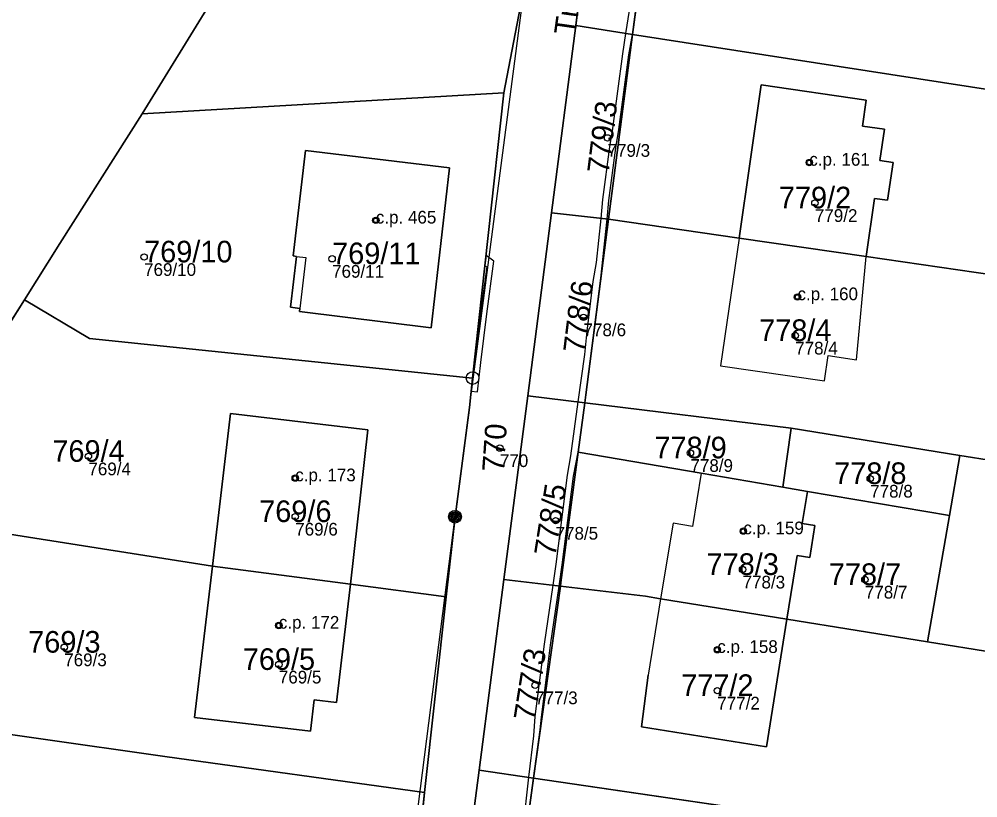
# Model space of a CAD drawing. Extents: x -603967 to -594699, y -1179315 to -1165625.
# Drawn here: x -597987.7 to -597912.3, y -1172213.4 to -1172152.2 of the extents above; entities that cross this region are included whole.
import ezdxf

# ---------------------------------------------------------------- set-up
doc = ezdxf.new("R2010")
doc.units = 0
for name, color, linetype in [('Definiční body', 7, 'Continuous'), ('Hranice parcel', 7, 'Continuous'), ('Parcelní čísla', 7, 'Continuous'), ('Polygon budovy', 7, 'Continuous'), ('Polygon parcely', 7, 'Continuous'), ('Pop  PČ popisy', 7, 'Continuous'), ('Poz předměty', 7, 'Continuous'), ('Vnitřní kresba', 7, 'Continuous'), ('Věcná břemena k části', 7, 'Continuous'), ('Značky bodu BP', 7, 'Continuous'), ('Značky budov', 7, 'Continuous')]:
    doc.layers.add(name, color=color, linetype=linetype)

msp = doc.modelspace()

# ---------------------------------------------------------------- linework, layer by layer
at = {"layer": 'Definiční body'}
for centre in [(-597941.45, -1172161.52994), (-597925.58, -1172163.46994), (-597925.14, -1172166.64994), (-597959.68, -1172168.01994), (-597977.91, -1172170.89994), (-597963.12, -1172171.03994), (-597926.51, -1172174.04994), (-597943.34, -1172175.63994), (-597926.69, -1172177.07994), (-597982.29, -1172186.57994), (-597949.92, -1172185.92994), (-597934.93, -1172186.30994), (-597966.02, -1172188.28994), (-597920.79, -1172188.32994), (-597966.02, -1172191.31994), (-597945.54, -1172191.63994), (-597930.77, -1172192.45994), (-597930.83, -1172195.47994), (-597921.21, -1172196.26994), (-597967.31, -1172199.87994), (-597984.19, -1172201.58994), (-597932.82, -1172201.78994), (-597967.31, -1172202.94994), (-597947.15, -1172204.57994), (-597932.82, -1172204.99994)]:
    msp.add_circle(centre, 0.25, dxfattribs=at)
at = {"layer": 'Hranice parcel'}
for p, q in [((-597978.05, -1172159.64), (-597964.77, -1172138.05)), ((-597943.96, -1172152.7), (-597941.99, -1172137.45)), ((-597937.48, -1172138.07), (-597939.48, -1172153.39)), ((-597949.61, -1172157.98), (-597947.92, -1172149.24)), ((-597945.87, -1172167.43), (-597943.96, -1172152.7)), ((-597939.48, -1172153.39), (-597943.96, -1172152.7)), ((-597941.37, -1172167.93), (-597939.48, -1172153.39)), ((-597939.48, -1172153.39), (-597904.76, -1172158.77)), ((-597978.05, -1172159.64), (-597949.61, -1172157.98)), ((-597949.61, -1172157.98), (-597952.07, -1172180.42)), ((-597947.73, -1172181.82), (-597945.87, -1172167.43)), ((-597941.37, -1172167.93), (-597945.87, -1172167.43)), ((-597998, -1172191.21), (-597987.33, -1172174.26)), ((-597949.6, -1172196.27), (-597947.73, -1172181.82)), ((-597943.24, -1172182.37), (-597947.73, -1172181.82)), ((-597943.76, -1172186.24), (-597943.24, -1172182.37)), ((-597943.24, -1172182.37), (-597927, -1172184.35)), ((-597927, -1172184.35), (-597927.66, -1172189)), ((-597927, -1172184.35), (-597913.74, -1172186.5)), ((-597943.76, -1172186.24), (-597945.12, -1172196.5)), ((-597913.74, -1172186.5), (-597914.56, -1172191.24)), ((-597925.73, -1172189.33), (-597927.66, -1172189)), ((-597914.56, -1172191.24), (-597925.73, -1172189.33)), ((-597914.56, -1172191.24), (-597916.27, -1172201.17)), ((-597972.54, -1172195.22), (-597993.35, -1172191.94)), ((-597961.68, -1172196.64), (-597972.54, -1172195.22)), ((-597954.14, -1172197.63), (-597961.68, -1172196.64)), ((-597951.54, -1172211.26), (-597949.6, -1172196.27)), ((-597945.16, -1172196.79), (-597949.6, -1172196.27)), ((-597945.16, -1172196.79), (-597947.27, -1172211.88)), ((-597945.12, -1172196.5), (-597945.16, -1172196.79)), ((-597955.84, -1172213.01), (-597954.14, -1172197.63)), ((-597927.34, -1172199.38), (-597937.28, -1172197.77)), ((-597916.27, -1172201.17), (-597927.34, -1172199.38)), ((-597947.27, -1172211.88), (-597951.54, -1172211.26)), ((-597949.23, -1172226.15), (-597947.27, -1172211.88)), ((-597947.27, -1172211.88), (-597911.97, -1172217.04)), ((-597955.84, -1172213.01), (-597957.24, -1172226))]:
    msp.add_line(p, q, dxfattribs=at)
for points in [[(-597987.33, -1172174.26), (-597984.55, -1172169.83), (-597978.05, -1172159.64)], [(-597965.65, -1172174.94), (-597966.39, -1172174.85), (-597965.93, -1172170.85), (-597966.18, -1172170.82), (-597965.22, -1172162.52), (-597953.89, -1172163.89), (-597955.34, -1172176.47), (-597965.68, -1172175.19), (-597965.65, -1172174.94)], [(-597941.37, -1172167.93), (-597943.16, -1172181.73), (-597943.24, -1172182.37)], [(-597903.91, -1172173.35), (-597909.56, -1172172.53), (-597921.11, -1172170.86), (-597931.11, -1172169.41), (-597941.37, -1172167.93)], [(-597952.07, -1172180.42), (-597982.2, -1172177.32), (-597987.33, -1172174.26)], [(-597954.14, -1172197.63), (-597953.45, -1172191.33), (-597952.32, -1172182.74), (-597952.07, -1172180.42)], [(-597972.54, -1172195.22), (-597971.12, -1172183.2), (-597960.3, -1172184.48), (-597961.68, -1172196.64)], [(-597927.66, -1172189), (-597934.1, -1172187.9), (-597943.76, -1172186.24)], [(-597905.59, -1172187.82), (-597908.43, -1172187.36), (-597913.74, -1172186.5)], [(-597927.34, -1172199.38), (-597926.54, -1172194.37), (-597925.55, -1172194.53), (-597925.14, -1172192.01), (-597926.13, -1172191.85), (-597925.73, -1172189.33)], [(-597961.68, -1172196.64), (-597962.78, -1172205.93), (-597964.52, -1172205.72), (-597964.82, -1172208.2), (-597973.95, -1172207.12), (-597972.54, -1172195.22)], [(-597937.28, -1172197.77), (-597938.47, -1172197.57), (-597945.16, -1172196.79)], [(-597910.16, -1172202.16), (-597911.07, -1172202.01), (-597916.27, -1172201.17)], [(-597996.18, -1172207.34), (-597976.28, -1172210.18), (-597955.84, -1172213.01)], [(-597953.39, -1172225.43), (-597952.04, -1172215.07), (-597951.54, -1172211.26)]]:
    msp.add_lwpolyline(points, dxfattribs=at)
at = {"layer": 'Polygon budovy'}
for points in [[(-597931.11, -1172169.41), (-597921.11, -1172170.86), (-597920.46, -1172166.29), (-597919.42, -1172166.44), (-597918.99, -1172163.47), (-597920.03, -1172163.32), (-597919.67, -1172160.85), (-597921.4, -1172160.6), (-597921.11, -1172158.57), (-597929.37, -1172157.37)], [(-597966.18, -1172170.82), (-597965.93, -1172170.85), (-597965.19, -1172170.93), (-597965.65, -1172174.94), (-597965.68, -1172175.19), (-597955.34, -1172176.47), (-597953.89, -1172163.89), (-597965.22, -1172162.52)], [(-597931.11, -1172169.41), (-597932.56, -1172179.46), (-597924.39, -1172180.63), (-597924.11, -1172178.65), (-597921.88, -1172178.98), (-597921.11, -1172170.86)], [(-597972.54, -1172195.22), (-597961.68, -1172196.64), (-597960.3, -1172184.48), (-597971.12, -1172183.2)], [(-597927.34, -1172199.38), (-597926.54, -1172194.37), (-597925.55, -1172194.53), (-597925.14, -1172192.01), (-597926.13, -1172191.85), (-597925.73, -1172189.33), (-597927.66, -1172189), (-597934.1, -1172187.9), (-597934.78, -1172192.09), (-597936.3, -1172191.84), (-597937.28, -1172197.77)], [(-597973.95, -1172207.12), (-597964.82, -1172208.2), (-597964.52, -1172205.72), (-597962.78, -1172205.93), (-597961.68, -1172196.64), (-597972.54, -1172195.22)], [(-597938.78, -1172207.86), (-597928.94, -1172209.43), (-597927.34, -1172199.38), (-597937.28, -1172197.77), (-597938.25, -1172203.79)]]:
    msp.add_lwpolyline(points, close=True, dxfattribs=at)
at = {"layer": 'Polygon parcely'}
for points in [[(-597964.77, -1172138.05), (-597950.03, -1172113.6), (-597977.95, -1172106.04), (-598024.89, -1172188.58), (-597998, -1172191.21), (-597987.33, -1172174.26), (-597984.55, -1172169.83), (-597978.05, -1172159.64)], [(-597943.37, -1172116.01), (-597944.91, -1172113.97), (-597946.07, -1172113.66), (-597949.44, -1172112.75), (-597950.03, -1172113.6), (-597964.77, -1172138.05), (-597978.05, -1172159.64), (-597949.61, -1172157.98), (-597947.92, -1172149.24)], [(-597941.99, -1172137.45), (-597943.96, -1172152.7), (-597939.48, -1172153.39), (-597937.48, -1172138.07)], [(-597937.48, -1172138.07), (-597939.48, -1172153.39), (-597904.76, -1172158.77), (-597904.04, -1172153.64), (-597902.59, -1172143.24), (-597906.05, -1172142.72), (-597916.63, -1172141.16), (-597926.68, -1172139.67)], [(-597939.48, -1172153.39), (-597943.96, -1172152.7), (-597945.87, -1172167.43), (-597941.37, -1172167.93)], [(-597941.37, -1172167.93), (-597931.11, -1172169.41), (-597921.11, -1172170.86), (-597909.56, -1172172.53), (-597903.91, -1172173.35), (-597902.56, -1172161.8), (-597902.22, -1172159.16), (-597904.76, -1172158.77), (-597939.48, -1172153.39)], [(-597978.05, -1172159.64), (-597984.55, -1172169.83), (-597987.33, -1172174.26), (-597982.2, -1172177.32), (-597952.07, -1172180.42), (-597949.61, -1172157.98)], [(-597965.65, -1172174.94), (-597965.68, -1172175.19), (-597955.34, -1172176.47), (-597953.89, -1172163.89), (-597965.22, -1172162.52), (-597966.18, -1172170.82), (-597965.93, -1172170.85), (-597966.39, -1172174.85)], [(-597965.65, -1172174.94), (-597966.39, -1172174.85), (-597965.93, -1172170.85), (-597966.18, -1172170.82), (-597965.22, -1172162.52), (-597953.89, -1172163.89), (-597955.34, -1172176.47), (-597965.68, -1172175.19)], [(-597945.87, -1172167.43), (-597947.73, -1172181.82), (-597943.24, -1172182.37), (-597943.16, -1172181.73), (-597941.37, -1172167.93)], [(-597927, -1172184.35), (-597913.74, -1172186.5), (-597908.43, -1172187.36), (-597905.59, -1172187.82), (-597905.04, -1172183.09), (-597903.91, -1172173.35), (-597909.56, -1172172.53), (-597921.11, -1172170.86), (-597931.11, -1172169.41), (-597941.37, -1172167.93), (-597943.16, -1172181.73), (-597943.24, -1172182.37)], [(-597953.45, -1172191.33), (-597952.32, -1172182.74), (-597952.07, -1172180.42), (-597982.2, -1172177.32), (-597987.33, -1172174.26), (-597998, -1172191.21), (-597993.35, -1172191.94), (-597972.54, -1172195.22), (-597971.12, -1172183.2), (-597960.3, -1172184.48), (-597961.68, -1172196.64), (-597954.14, -1172197.63)], [(-597943.24, -1172182.37), (-597947.73, -1172181.82), (-597949.6, -1172196.27), (-597945.16, -1172196.79), (-597945.12, -1172196.5), (-597943.76, -1172186.24)], [(-597943.24, -1172182.37), (-597943.76, -1172186.24), (-597934.1, -1172187.9), (-597927.66, -1172189), (-597927, -1172184.35)], [(-597961.68, -1172196.64), (-597960.3, -1172184.48), (-597971.12, -1172183.2), (-597972.54, -1172195.22)], [(-597927.66, -1172189), (-597925.73, -1172189.33), (-597914.56, -1172191.24), (-597913.74, -1172186.5), (-597927, -1172184.35)], [(-597943.76, -1172186.24), (-597945.12, -1172196.5), (-597945.16, -1172196.79), (-597938.47, -1172197.57), (-597937.28, -1172197.77), (-597927.34, -1172199.38), (-597926.54, -1172194.37), (-597925.55, -1172194.53), (-597925.14, -1172192.01), (-597926.13, -1172191.85), (-597925.73, -1172189.33), (-597927.66, -1172189), (-597934.1, -1172187.9)], [(-597916.27, -1172201.17), (-597911.07, -1172202.01), (-597910.16, -1172202.16), (-597871.52, -1172208.41), (-597869.04, -1172193.74), (-597905.59, -1172187.82), (-597908.43, -1172187.36), (-597913.74, -1172186.5), (-597914.56, -1172191.24)], [(-597925.73, -1172189.33), (-597926.13, -1172191.85), (-597925.14, -1172192.01), (-597925.55, -1172194.53), (-597926.54, -1172194.37), (-597927.34, -1172199.38), (-597916.27, -1172201.17), (-597914.56, -1172191.24)], [(-597964.82, -1172208.2), (-597973.95, -1172207.12), (-597972.54, -1172195.22), (-597993.35, -1172191.94), (-598002.14, -1172206.39), (-597996.18, -1172207.34), (-597976.28, -1172210.18), (-597955.84, -1172213.01), (-597954.14, -1172197.63), (-597961.68, -1172196.64), (-597962.78, -1172205.93), (-597964.52, -1172205.72)], [(-597972.54, -1172195.22), (-597973.95, -1172207.12), (-597964.82, -1172208.2), (-597964.52, -1172205.72), (-597962.78, -1172205.93), (-597961.68, -1172196.64)], [(-597949.6, -1172196.27), (-597951.54, -1172211.26), (-597947.27, -1172211.88), (-597945.16, -1172196.79)], [(-597911.07, -1172202.01), (-597916.27, -1172201.17), (-597927.34, -1172199.38), (-597937.28, -1172197.77), (-597938.47, -1172197.57), (-597945.16, -1172196.79), (-597947.27, -1172211.88), (-597911.97, -1172217.04), (-597910.16, -1172202.16)], [(-597964.63, -1172224.94), (-597957.24, -1172226), (-597955.84, -1172213.01), (-597976.28, -1172210.18), (-597996.18, -1172207.34), (-597997.29, -1172216.06), (-597975.12, -1172223.43), (-597973.83, -1172214.15), (-597963.34, -1172215.61), (-597963.78, -1172218.82), (-597962.6, -1172218.99), (-597962.98, -1172221.7), (-597964.16, -1172221.58)], [(-597949.23, -1172226.15), (-597947.27, -1172211.88), (-597951.54, -1172211.26), (-597952.04, -1172215.07), (-597953.39, -1172225.43)], [(-597929.15, -1172229.61), (-597913.82, -1172232.25), (-597911.97, -1172217.04), (-597947.27, -1172211.88), (-597949.23, -1172226.15), (-597947.84, -1172226.39), (-597940.09, -1172227.73), (-597938.27, -1172217.37), (-597927.36, -1172219.26)]]:
    msp.add_lwpolyline(points, close=True, dxfattribs=at)
for points in [[(-597952.04, -1172215.07), (-597951.54, -1172211.26), (-597949.6, -1172196.27), (-597947.73, -1172181.82), (-597945.87, -1172167.43), (-597943.96, -1172152.7), (-597941.99, -1172137.45)], [(-597947.92, -1172149.24), (-597949.61, -1172157.98), (-597952.07, -1172180.42), (-597952.32, -1172182.74), (-597953.45, -1172191.33), (-597954.14, -1172197.63), (-597955.84, -1172213.01), (-597957.24, -1172226)]]:
    msp.add_lwpolyline(points, dxfattribs=at)
at = {"layer": 'Poz předměty'}
for p, q in [((-597953.45, -1172191.33), (-597947.92, -1172149.24)), ((-597958.82, -1172233.47), (-597953.45, -1172191.33))]:
    msp.add_line(p, q, dxfattribs=at)
for radius in [0.5, 0.4, 0.3, 0.2, 0.1]:
    msp.add_circle((-597953.45343, -1172191.32988), radius, dxfattribs=at)
at = {"layer": 'Vnitřní kresba'}
for p, q in [((-597931.11, -1172169.41), (-597929.37, -1172157.37)), ((-597929.37, -1172157.37), (-597921.11, -1172158.57)), ((-597921.11, -1172158.57), (-597921.4, -1172160.6)), ((-597921.4, -1172160.6), (-597919.67, -1172160.85)), ((-597919.67, -1172160.85), (-597920.03, -1172163.32)), ((-597920.03, -1172163.32), (-597918.99, -1172163.47)), ((-597918.99, -1172163.47), (-597919.42, -1172166.44)), ((-597920.46, -1172166.29), (-597921.11, -1172170.86)), ((-597919.42, -1172166.44), (-597920.46, -1172166.29)), ((-597931.11, -1172169.41), (-597932.56, -1172179.46)), ((-597965.93, -1172170.85), (-597965.19, -1172170.93)), ((-597965.19, -1172170.93), (-597965.65, -1172174.94)), ((-597921.88, -1172178.98), (-597921.11, -1172170.86)), ((-597924.39, -1172180.63), (-597924.11, -1172178.65)), ((-597924.11, -1172178.65), (-597921.88, -1172178.98)), ((-597932.56, -1172179.46), (-597924.39, -1172180.63)), ((-597934.1, -1172187.9), (-597934.78, -1172192.09)), ((-597936.3, -1172191.84), (-597937.28, -1172197.77)), ((-597934.78, -1172192.09), (-597936.3, -1172191.84)), ((-597937.28, -1172197.77), (-597938.25, -1172203.79)), ((-597927.34, -1172199.38), (-597928.94, -1172209.43)), ((-597938.78, -1172207.86), (-597938.25, -1172203.79)), ((-597928.94, -1172209.43), (-597938.78, -1172207.86))]:
    msp.add_line(p, q, dxfattribs=at)
at = {"layer": 'Věcná břemena k části'}
for points in [[(-597948.69, -1172222.24), (-597947.27, -1172211.88), (-597946.74, -1172208.08), (-597946.66, -1172207.09), (-597945.93, -1172201.42), (-597945.26, -1172196.78), (-597945.02, -1172195.12), (-597944.14, -1172188.14), (-597943.76, -1172186.24), (-597943.24, -1172182.37), (-597943.16, -1172181.73), (-597941.97, -1172172.57), (-597941.49, -1172167.92), (-597941.34, -1172166.45), (-597940.79, -1172162.32), (-597940.57, -1172160.87), (-597939.78, -1172155), (-597939.48, -1172153.39), (-597937.48, -1172138.07)], [(-597939.37, -1172149.02), (-597940.03, -1172153.31), (-597940.28, -1172154.92), (-597941.07, -1172160.79), (-597941.29, -1172162.24), (-597941.84, -1172166.39), (-597941.99, -1172167.86), (-597942.35, -1172171.33), (-597942.62, -1172172.83), (-597943.08, -1172176.74), (-597943.27, -1172178.56), (-597943.79, -1172182.3), (-597944.37, -1172186.55), (-597944.64, -1172188.06), (-597945.52, -1172195.06), (-597945.76, -1172196.72), (-597946.43, -1172201.36), (-597947.16, -1172207.03), (-597947.28, -1172208.56), (-597947.66, -1172211.82), (-597948.12, -1172215.85)]]:
    msp.add_lwpolyline(points, dxfattribs=at)
msp.add_lwpolyline([(-597952.18, -1172181.44), (-597951.67, -1172181.5), (-597951.43, -1172179.19), (-597950.95, -1172175.37), (-597950.39, -1172171.23), (-597951.01, -1172170.77), (-597951.1, -1172171.58), (-597950.96, -1172171.67), (-597951.45, -1172175.31), (-597951.93, -1172179.13), (-597952.07, -1172180.42)], close=True, dxfattribs=at)
at = {"layer": 'Značky bodu BP'}
for radius in [0.5, 0.0303]:
    msp.add_circle((-597952.07, -1172180.41988), radius, dxfattribs=at)
at = {"layer": 'Značky budov'}
for centre in [(-597925.5868, -1172163.46916), (-597959.6868, -1172168.01916), (-597926.5168, -1172174.04916), (-597966.0268, -1172188.28916), (-597930.7768, -1172192.45916), (-597967.3168, -1172199.87916), (-597932.8268, -1172201.78916)]:
    msp.add_circle(centre, 0.175, dxfattribs=at)

# ---------------------------------------------------------------- texts
at = {"layer": 'Definiční body'}
for s, p in [('779/3', (-597941.45, -1172163.019)), ('c.p. 161', (-597925.58, -1172163.72)), ('c.p. 465', (-597959.68, -1172168.27)), ('779/2', (-597925.14, -1172168.139)), ('769/10', (-597977.91, -1172172.389)), ('769/11', (-597963.12, -1172172.529)), ('c.p. 160', (-597926.51, -1172174.3)), ('778/6', (-597943.34, -1172177.129)), ('778/4', (-597926.69, -1172178.569)), ('770', (-597949.92, -1172187.419)), ('769/4', (-597982.29, -1172188.069)), ('778/9', (-597934.93, -1172187.799)), ('c.p. 173', (-597966.02, -1172188.54)), ('778/8', (-597920.79, -1172189.819)), ('769/6', (-597966.02, -1172192.809)), ('778/5', (-597945.54, -1172193.129)), ('c.p. 159', (-597930.77, -1172192.71)), ('778/3', (-597930.83, -1172196.969)), ('778/7', (-597921.21, -1172197.759)), ('c.p. 172', (-597967.31, -1172200.13)), ('c.p. 158', (-597932.82, -1172202.04)), ('769/3', (-597984.19, -1172203.079)), ('769/5', (-597967.31, -1172204.439)), ('777/3', (-597947.15, -1172206.069)), ('777/2', (-597932.82, -1172206.489))]:
    msp.add_text(s, height=0.999996, dxfattribs=at).set_placement(p)
at = {"layer": 'Parcelní čísla'}
for s, rotation, p in [('779/3', 83, (-597941.373, -1172164.396)), ('778/6', 83, (-597943.263, -1172178.506)), ('770', 86, (-597949.627, -1172187.845)), ('778/5', 81, (-597945.563, -1172194.507)), ('777/3', 81, (-597947.173, -1172207.447))]:
    msp.add_text(s, height=1.699998, rotation=rotation, dxfattribs=at).set_placement(p)
for s, p in [('779/2', (-597927.976, -1172167.075)), ('769/10', (-597977.91, -1172171.325)), ('769/11', (-597963.12, -1172171.465)), ('778/4', (-597929.526, -1172177.505)), ('769/4', (-597985.126, -1172187.005)), ('778/9', (-597937.766, -1172186.735)), ('778/8', (-597923.626, -1172188.755)), ('769/6', (-597968.856, -1172191.745)), ('778/3', (-597933.666, -1172195.905)), ('778/7', (-597924.046, -1172196.695)), ('769/3', (-597987.026, -1172202.015)), ('769/5', (-597970.146, -1172203.375)), ('777/2', (-597935.656, -1172205.425))]:
    msp.add_text(s, height=1.699998, dxfattribs=at).set_placement(p)
at = {"layer": 'Pop  PČ popisy'}
msp.add_text('Trávníky', height=1.699998, rotation=82, dxfattribs=at).set_placement((-597943.986, -1172153.515))

doc.saveas('drawing.dxf')
